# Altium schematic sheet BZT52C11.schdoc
size 127 x 101 mm
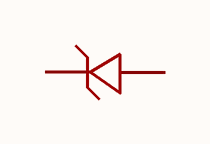
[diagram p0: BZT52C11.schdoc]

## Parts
D?  bzt52c11_c173430  [SOD-123_L2.7-W1.6-LS3.7-RD]  (value not drawn)

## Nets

Not connected (* = marked no-connect by the designer): D? 1(K) 2(A)

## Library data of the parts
D? = bzt52c11_c173430: 二极管配置:1个独立式;稳压值(标称值):11V;稳压值(范围值):10.45V~11.55V;耗散功率(Pd):500mW;; Manufacturer: MDD(辰达半导体); AddInBom: yes; ModelId: ad7e39f9e5534b3c96ffdc5532ebb493; ModelName: SOD-123_L2.7-W1.6-H1.4-LS3.7; ModelTransform: 146.026,62.992,0,180,0,0,0.0005,0,0; Diode Configuration: 1个独立式; Zener Voltage(Nom): 11V; Reverse Leakage Current (Ir): 100nA@8V; Pd - Power Dissipation: 500mW; Impedance(Zzt): 30Ω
